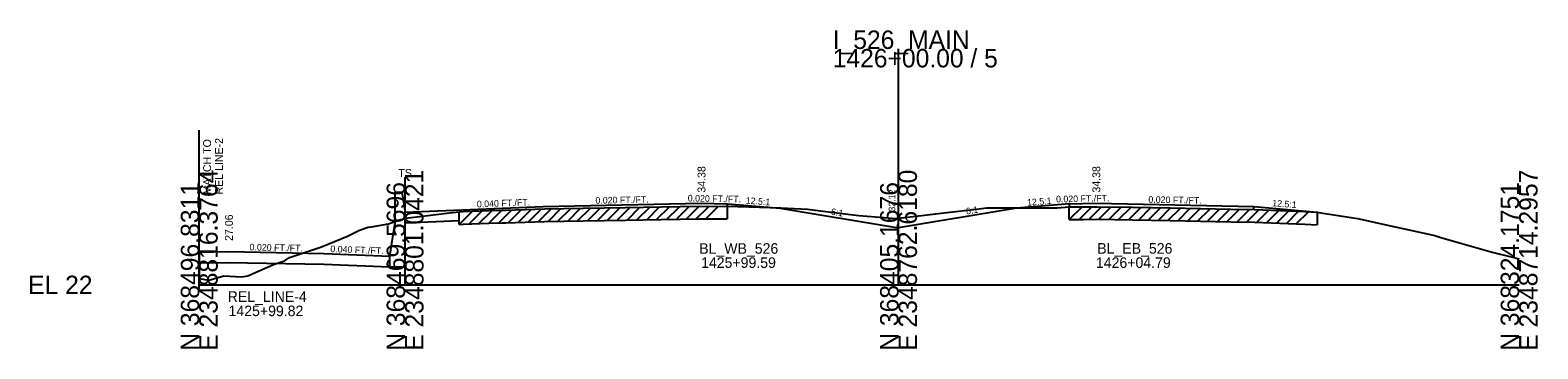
# Model space of a CAD drawing. Extents: x -170 to 2527928, y -10 to 1619750.
# Drawn here: x 3974.3 to 4203.4, y 4490.3 to 4538.6 of the extents above; entities that cross this region are included whole.
import ezdxf

# ---------------------------------------------------------------- set-up
doc = ezdxf.new("R2010")
doc.units = 0
for name, color, linetype in [('RD_GPK_XS_Cell', 7, 'Continuous'), ('RD_PD_NOISE-WALL-GM', 7, 'Continuous'), ('RD_XS_Base', 7, 'Continuous'), ('RD_XS_EarthShd', 7, 'Continuous'), ('RD_XS_ExGround', 7, 'Continuous'), ('RD_XS_ExPaveRet', 7, 'Continuous'), ('RD_XS_MatchLine', 7, 'Continuous'), ('RD_XS_Pave', 7, 'Continuous'), ('RD_XS_PaveShd', 7, 'Continuous'), ('RD_XS_TieSlope', 7, 'Continuous'), ('RD_XS_TX_Elev_EX', 7, 'Continuous'), ('RD_XS_TX_Slope', 7, 'Continuous'), ('RD_XS_TX_Station', 7, 'Continuous')]:
    doc.layers.add(name, color=color, linetype=linetype)

msp = doc.modelspace()

# ---------------------------------------------------------------- linework, layer by layer
at = {"layer": 'RD_GPK_XS_Cell'}
for p, q in [((4106.27, 4500), (4106.27, 4535.8)), ((4000, 4500), (4031.28, 4500)), ((4031.28, 4500), (4106.27, 4500)), ((4106.27, 4500), (4200.58, 4500))]:
    msp.add_line(p, q, dxfattribs=at)
at = {"layer": 'RD_PD_NOISE-WALL-GM'}
for p, q in [((4029.72, 4514.06), (4030.8, 4514.06)), ((4029.72, 4514.06), (4029.72, 4509.18)), ((4030.8, 4514.06), (4031.28, 4511.06)), ((4028.95, 4504.37), (4029.72, 4509.18)), ((4031.28, 4502.73), (4031.28, 4511.06)), ((4028.95, 4502.73), (4028.95, 4504.37)), ((4028.95, 4502.73), (4031.28, 4502.73))]:
    msp.add_line(p, q, dxfattribs=at)
at = {"layer": 'RD_XS_Base'}
for p, q in [((4080.27, 4511.93), (4080.27, 4512.3)), ((4132.27, 4511.83), (4132.27, 4512.3)), ((4160.27, 4511.45), (4160.27, 4511.9)), ((4031.28, 4509.42), (4039.51, 4509.75)), ((4000, 4503.33), (4004.46, 4503.42)), ((4004.46, 4503.42), (4018.95, 4503.13)), ((4018.95, 4503.13), (4028.95, 4502.73))]:
    msp.add_line(p, q, dxfattribs=at)
at = {"layer": 'RD_XS_EarthShd'}
for p, q in [((4080.27, 4512.3), (4088.27, 4511.66)), ((4132.27, 4512.3), (4124.27, 4511.66)), ((4160.27, 4511.9), (4169.88, 4511.05))]:
    msp.add_line(p, q, dxfattribs=at)
at = {"layer": 'RD_XS_ExGround'}
msp.add_lwpolyline([(4000, 4500.97), (4001.45, 4500.7), (4003.72, 4501.38), (4006.43, 4501.22), (4007.39, 4501.36), (4011.27, 4503.12), (4012.95, 4503.66), (4013.73, 4504.17), (4018.58, 4505.76), (4022.52, 4507.37), (4024.34, 4508.29), (4025.69, 4508.76), (4026.16, 4508.81), (4028.75, 4509.26), (4030.44, 4509.85), (4031.28, 4510.06), (4031.77, 4510.18), (4033.92, 4510.42), (4038.01, 4510.93), (4039.51, 4511.11), (4040.09, 4511.14), (4044.02, 4511.27), (4046.03, 4511.34), (4046.57, 4511.36), (4052.45, 4511.53), (4058.34, 4511.63), (4064.76, 4511.74), (4070.22, 4511.83), (4075.97, 4511.93), (4077.35, 4511.92), (4080.21, 4511.93), (4088.37, 4511.71), (4092.46, 4511.5), (4095.64, 4511.11), (4100.25, 4510.51), (4104.06, 4510.24), (4105.93, 4510.08), (4106.27, 4510.12), (4108.95, 4510.42), (4111.9, 4510.8), (4113.59, 4510.99), (4118.12, 4511.5), (4119.66, 4511.69), (4121.95, 4511.71), (4130.39, 4511.69), (4132.22, 4511.83), (4134.31, 4511.86), (4136.38, 4511.87), (4141.85, 4511.77), (4147.56, 4511.67), (4156.77, 4511.51), (4160.38, 4511.45), (4168.02, 4511.13), (4169.88, 4511.05), (4170.47, 4510.96), (4176, 4510.1), (4181.75, 4508.82), (4184.09, 4508.31), (4187.76, 4507.51), (4188.69, 4507.21), (4196.49, 4504.96), (4199.37, 4504.26), (4200.58, 4503.97)], dxfattribs=at)
at = {"layer": 'RD_XS_ExPaveRet'}
for p, q in [((4044.01, 4509.36), (4046, 4511.34)), ((4045.51, 4509.41), (4047.49, 4511.39)), ((4047.01, 4509.45), (4048.98, 4511.43)), ((4048.51, 4509.5), (4050.48, 4511.47)), ((4050.01, 4509.54), (4051.98, 4511.51)), ((4051.51, 4509.58), (4053.47, 4511.55)), ((4053.01, 4509.62), (4054.96, 4511.57)), ((4054.51, 4509.65), (4056.46, 4511.6)), ((4056.01, 4509.67), (4057.96, 4511.63)), ((4057.51, 4509.7), (4059.46, 4511.65)), ((4059.01, 4509.73), (4060.96, 4511.68)), ((4060.51, 4509.75), (4062.46, 4511.7)), ((4062.01, 4509.78), (4063.96, 4511.73)), ((4063.51, 4509.8), (4065.46, 4511.75)), ((4065.01, 4509.83), (4066.96, 4511.77)), ((4066.51, 4509.85), (4068.46, 4511.8)), ((4068.01, 4509.87), (4069.96, 4511.82)), ((4069.51, 4509.9), (4071.46, 4511.85)), ((4071.01, 4509.92), (4072.96, 4511.87)), ((4072.51, 4509.95), (4074.46, 4511.9)), ((4074.01, 4509.98), (4075.96, 4511.93)), ((4075.51, 4510), (4077.43, 4511.92)), ((4077.01, 4510.01), (4078.93, 4511.93)), ((4080.21, 4511.93), (4080.21, 4510.02)), ((4132.22, 4509.91), (4134.16, 4511.85)), ((4132.22, 4509.91), (4132.22, 4511.83)), ((4133.72, 4509.93), (4135.66, 4511.87)), ((4135.22, 4509.95), (4137.13, 4511.86)), ((4136.72, 4509.95), (4138.6, 4511.83)), ((4138.22, 4509.92), (4140.1, 4511.81)), ((4139.72, 4509.9), (4141.6, 4511.78)), ((4141.22, 4509.87), (4143.1, 4511.75)), ((4142.72, 4509.84), (4144.6, 4511.72)), ((4144.22, 4509.81), (4146.1, 4511.69)), ((4145.72, 4509.78), (4147.6, 4511.67)), ((4147.22, 4509.76), (4149.1, 4511.64)), ((4148.72, 4509.73), (4150.61, 4511.62)), ((4150.22, 4509.71), (4152.11, 4511.59)), ((4151.72, 4509.68), (4153.61, 4511.56)), ((4153.22, 4509.65), (4155.11, 4511.54)), ((4154.72, 4509.63), (4156.61, 4511.51)), ((4156.22, 4509.6), (4158.11, 4511.49)), ((4157.72, 4509.58), (4159.61, 4511.46)), ((4159.22, 4509.55), (4161.09, 4511.42)), ((4160.72, 4509.52), (4162.56, 4511.36)), ((4039.51, 4509.19), (4041.51, 4511.19)), ((4039.51, 4509.19), (4039.51, 4511.11)), ((4039.51, 4509.19), (4040.09, 4509.22)), ((4040.09, 4509.22), (4044.02, 4509.36)), ((4041.01, 4509.25), (4043, 4511.24)), ((4042.51, 4509.31), (4044.5, 4511.29)), ((4044.02, 4509.36), (4046.03, 4509.43)), ((4046.03, 4509.43), (4046.57, 4509.44)), ((4046.57, 4509.44), (4052.45, 4509.61)), ((4052.45, 4509.61), (4058.34, 4509.72)), ((4058.34, 4509.72), (4064.76, 4509.82)), ((4064.76, 4509.82), (4070.22, 4509.91)), ((4070.22, 4509.91), (4075.97, 4510.01)), ((4075.97, 4510.01), (4077.35, 4510.01)), ((4077.35, 4510.01), (4080.21, 4510.02)), ((4132.22, 4509.91), (4134.31, 4509.94)), ((4134.31, 4509.94), (4136.38, 4509.96)), ((4136.38, 4509.96), (4141.85, 4509.86)), ((4141.85, 4509.86), (4147.56, 4509.75)), ((4147.56, 4509.75), (4156.77, 4509.59)), ((4156.77, 4509.59), (4160.38, 4509.53)), ((4160.38, 4509.53), (4168.02, 4509.21)), ((4162.22, 4509.45), (4164.06, 4511.29)), ((4163.72, 4509.39), (4165.56, 4511.23)), ((4165.22, 4509.33), (4167.06, 4511.17)), ((4166.72, 4509.27), (4168.56, 4511.11)), ((4168.02, 4509.21), (4169.88, 4509.13)), ((4169.88, 4511.05), (4169.88, 4509.13))]:
    msp.add_line(p, q, dxfattribs=at)
at = {"layer": 'RD_XS_MatchLine'}
for p, q in [((4000, 4499.09), (4000, 4523.5)), ((4031.28, 4500), (4031.28, 4516.36))]:
    msp.add_line(p, q, dxfattribs=at)
at = {"layer": 'RD_XS_Pave'}
for p, q in [((4052.27, 4511.9), (4076.27, 4512.38)), ((4136.27, 4512.38), (4160.27, 4511.9)), ((4004.46, 4505.06), (4018.95, 4504.77))]:
    msp.add_line(p, q, dxfattribs=at)
at = {"layer": 'RD_XS_PaveShd'}
for p, q in [((4031.28, 4511.06), (4052.27, 4511.9)), ((4076.27, 4512.38), (4080.27, 4512.3)), ((4132.27, 4512.3), (4136.27, 4512.38)), ((4000, 4504.97), (4004.46, 4505.06)), ((4000, 4504.97), (4000, 4500.97)), ((4018.95, 4504.77), (4028.95, 4504.37))]:
    msp.add_line(p, q, dxfattribs=at)
at = {"layer": 'RD_XS_TieSlope'}
for p in [(4088.27, 4511.66), (4124.27, 4511.66)]:
    msp.add_line(p, (4106.27, 4508.66), dxfattribs=at)

# ---------------------------------------------------------------- texts
at = {"layer": 'RD_GPK_XS_Cell'}
for s, p in [('I_526_MAIN', (4096.27, 4535.8)), ('1426+00.00 / 5', (4096.27, 4533)), ('EL 22', (3974, 4498.6))]:
    msp.add_text(s, height=2.8, dxfattribs=at).set_placement(p)
for s, p in [('E 2348816.3764', (4002.8, 4490)), ('E 2348801.0421', (4034.08, 4490)), ('E 2348762.6180', (4109.07, 4490)), ('E 2348714.2957', (4203.38, 4490)), ('N 368496.8311', (4000, 4490)), ('N 368469.5696', (4031.28, 4490)), ('N 368405.1676', (4106.27, 4490)), ('N 368324.1751', (4200.58, 4490))]:
    msp.add_text(s, height=2.8, rotation=90, dxfattribs=at).set_placement(p)
at = {"layer": 'RD_XS_MatchLine'}
msp.add_text('TS', height=1.2, dxfattribs=at).set_placement((4030.27, 4516.38))
at = {"layer": 'RD_XS_TX_Elev_EX'}
msp.add_text('32.12', height=1, rotation=90, dxfattribs=at).set_placement((4105.77, 4511.12))
at = {"layer": 'RD_XS_TX_Slope'}
for s, rotation, p in [('0.020 FT./FT.', 358.8542, (4074.23, 4512.67)), ('0.020 FT./FT.', 1.1458, (4130.22, 4512.51)), ('0.040 FT./FT.', 2.2906, (4042.21, 4511.75)), ('0.020 FT./FT.', 1.1458, (4060.22, 4512.31)), ('12.5:1', 355.4261, (4083.03, 4512.34)), ('6:1', 350.5377, (4095.95, 4510.66)), ('6:1', 9.4623, (4116.6, 4510.67)), ('12.5:1', 4.5739, (4125.85, 4512)), ('0.020 FT./FT.', 358.8542, (4144.23, 4512.47)), ('12.5:1', 355.4261, (4163.03, 4511.94)), ('0.020 FT./FT.', 358.8542, (4007.65, 4505.24)), ('0.040 FT./FT.', 357.7094, (4019.91, 4504.98))]:
    msp.add_text(s, height=1, rotation=rotation, dxfattribs=at).set_placement(p)
at = {"layer": 'RD_XS_TX_Station'}
for s, p in [('MATCH TO', (4001.8, 4513.73)), ('REL LINE-2', (4003.6, 4513.73)), (' 34.38', (4076.93, 4513.55)), (' 34.38', (4136.93, 4513.56)), (' 27.06', (4005.11, 4506.23))]:
    msp.add_text(s, height=1.2, rotation=90, dxfattribs=at).set_placement(p)
for s, p in [('BL_WB_526', (4075.98, 4504.73)), ('BL_EB_526', (4136.47, 4504.74)), ('1425+99.59', (4076.27, 4502.58)), ('1426+04.79', (4136.27, 4502.58)), ('REL_LINE-4', (4004.33, 4497.43)), ('1425+99.82', (4004.46, 4495.26))]:
    msp.add_text(s, height=1.6, dxfattribs=at).set_placement(p)

doc.saveas('drawing.dxf')
